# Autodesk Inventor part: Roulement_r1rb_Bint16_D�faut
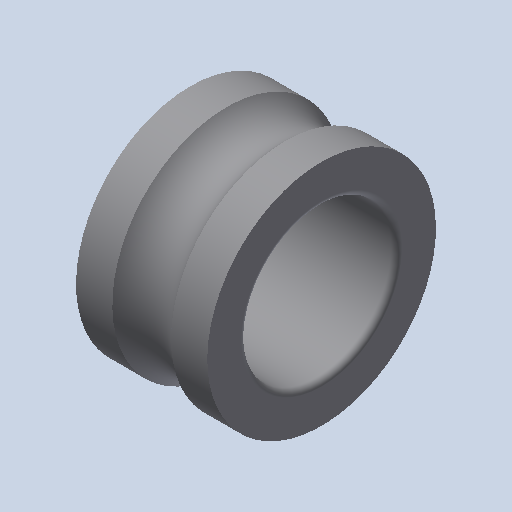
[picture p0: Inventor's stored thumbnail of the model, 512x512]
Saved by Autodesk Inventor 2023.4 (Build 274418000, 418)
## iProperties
Created: 2011-01
Part Number: Roulement_r1rb_Bint16_D�faut
Document SubType Name: Modeling
Designer: eric
Density: 1 g/cm^3
Mass: 0.409986 g
Surface Area: 5.7627 cm^2
Volume: 0.409986 cm^3
Material: Générique
Appearance: Par défaut
Author: eric
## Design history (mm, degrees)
feature "Base1"
node "Corps solides"
node "Corps surfaciques"
node "Solide1"
